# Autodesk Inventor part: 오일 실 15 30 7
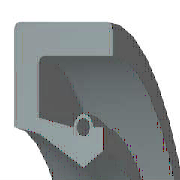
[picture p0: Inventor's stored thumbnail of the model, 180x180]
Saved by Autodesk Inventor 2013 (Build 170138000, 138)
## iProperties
IsCustomPart: 1
Created: 2012-02
Part Number: 오일 실 15 30 7
Material: 고무
Description: 오일-실
Document SubType Name: Modeling
Standard: KS B 2804
Designer: mduedu
Standards Organization: KS
Language: ko-KR
Size Designation: S - 15 30 7
Categories: <MemberInstance><Categories><Category DisplayName="샤프트 부품" InternalName="7f7aeb1f-a693-4053-b835-cee3144e0d98" Mnemonic="SHFT"><Category DisplayName="실링" Intern
Density: 0.93 g/cm^3
Author: mduedu
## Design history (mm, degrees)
revolve "본체" stored, may be unused: angle "d17" = 90 deg
revolve "스프링1" stored, may be unused: angle "d18" = 90 deg
body "Solid1"
sketch "스케치1"
  geometry: L1 (0, 15)-(7, 15); L2 (7, 15)-(7, 13.75); L3 (7, 13.75)-(1.75, 13.75); L4 (0, 15)-(0, 9.6); L5 (0, 9.6)-(1.75, 9.25); L6 (1.75, 9.25)-(4.9, 7.5); L7 (4.9, 7.5)-(0, 7.5); L8 (6.3, 8.375)-(6.3, 9.6); L9 (0, 0)-(9.586, 0) reference; L10 (4.9, 7.5)-(6.3, 8.375); L11 (0, 18)-(0, -3) reference; L12 (-1.917, 0)-(11.503, 0) reference; L13 (4.2, 9.6)-(1.75, 10.09); L14 (1.75, 10.09)-(1.75, 13.75); L15 (6.3, 9.6)-(5.6, 9.6); C1 r 0.455 at (4.9, 9.6); A1 r 0.7 centre (4.9, 9.6) between (5.6, 9.6) and (4.2, 9.6)
  constraints: 26 end point, 5 horizontal alignment, 4 perpendicular, 2 centre point, 2 collinear, 2 horizontal, 2 parallel, 2 point on circle, 2 point on line, 2 vertical alignment, 1 coincident
  dimensions: "d0" = 30 diameter of L1 L9 (= SD2); "d1" = 16.75 diameter of L8.start L9 (= ABDM); "d2" = 1.25 distance of L1.end L2.end (computed from SD); "d3" = 0.91 diameter of C1 (= SPDI); "d4" = 1.4 diameter of A1 (= SPDA); "d5" = 15 diameter of L6.end L9 (= NND); "d6" = 18.5 diameter of L5.end L9 (= TKDM); "d7" = 19.2 diameter of L4.end L9 (= HLDM); "d8" = 4.9 distance from line of C1.centre L4 (= SPDST); "d9" = 6.3 distance between parallel lines of L8 L4 (= SDI); "d10" = 7 distance between parallel lines of L2 L4 (= SWDT); "d12" = 1.75 distance between parallel lines of L14 L4 (= SD)
fillet "모깎기1" dims "d11" = 0.3 (= RR)
other parameters: "SD2" = 30 [user parameter; used in 1 equation term], "SWDT" = 7 [user parameter; used in 1 equation term], "RR" = 0.3 [user parameter; used in 1 equation term], "SD" = 1.75 [user parameter; used in 2 equation terms], "NND" = 15 [user parameter; used in 1 equation term], "SPDA" = 1.4 [user parameter; used in 1 equation term], "SPDI" = 0.91 [user parameter; used in 1 equation term], "TKDM" = 18.5 [user parameter; used in 1 equation term], "HLDM" = 19.2 [user parameter; used in 1 equation term], "ABDM" = 16.75 [user parameter; used in 1 equation term], "SDI" = 6.3 [user parameter; used in 1 equation term], "SPDST" = 4.9 [user parameter; used in 1 equation term], "d13" = 0, "d14" = 0, "d15" = 0, "LAB" = 0.35 [user parameter]
